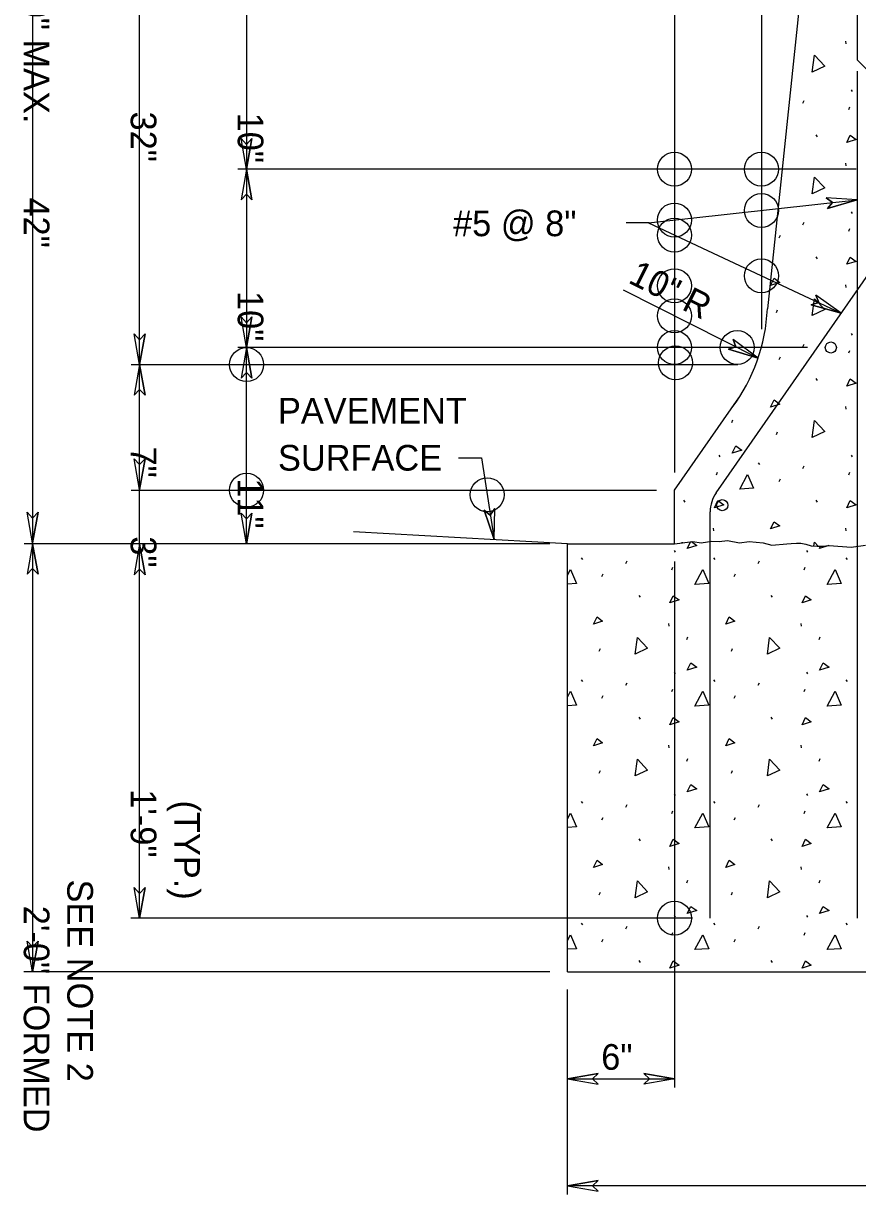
# Model space of a CAD drawing. Extents: x -26.5 to -19.2, y -3.6 to 6.6.
# Drawn here: x -25.3 to -23.351, y 0.225 to 2.961 of the extents above; entities that cross this region are included whole.
import ezdxf

# ---------------------------------------------------------------- set-up
doc = ezdxf.new("R2010")
doc.units = 0
for name, color, linetype in [('ANNO-WOUT', 7, 'Continuous'), ('DETL-DIMS', 7, 'Continuous'), ('DETL-PATT', 7, 'Continuous'), ('Level 10', 7, 'Continuous'), ('Level 12', 7, 'Continuous'), ('SECT-GRND_P', 7, 'Continuous'), ('SUBS-FOOT_P', 7, 'Continuous'), ('SUPR-PARA_P', 7, 'Continuous'), ('SUPR-RFRC', 7, 'Continuous')]:
    doc.layers.add(name, color=color, linetype=linetype)

msp = doc.modelspace()

# ---------------------------------------------------------------- linework, layer by layer
at = {"layer": 'ANNO-WOUT'}
for centre in [(-23.7787, 2.6205), (-23.5755, 2.6205), (-23.5755, 2.5241), (-23.7786, 2.5017), (-23.7786, 2.4664), (-23.5755, 2.3715), (-23.7787, 2.3482), (-23.7787, 2.2778), (-23.7787, 2.2039), (-23.6319, 2.2039), (-24.7787, 2.164), (-23.7761, 2.1681), (-24.7787, 1.8705), (-24.2163, 1.86), (-23.7787, 0.8705)]:
    msp.add_circle(centre, 0.0397, dxfattribs=at)
at = {"layer": 'DETL-DIMS'}
for p, q in [((-24.7787, 2.6205), (-24.7913, 2.692)), ((-24.7787, 2.6785), (-24.7913, 2.692)), ((-24.7787, 2.6205), (-24.7661, 2.692)), ((-24.7661, 2.692), (-24.7787, 2.6785)), ((-24.7787, 2.6205), (-24.7913, 2.549)), ((-24.7787, 2.6205), (-24.7661, 2.549)), ((-24.7787, 2.5625), (-24.7913, 2.549)), ((-24.7661, 2.549), (-24.7787, 2.5625)), ((-23.3516, 2.5488), (-23.424, 2.5535)), ((-23.4092, 2.5424), (-23.424, 2.5535)), ((-23.3516, 2.5488), (-23.4212, 2.5285)), ((-23.4212, 2.5285), (-23.4092, 2.5424)), ((-23.3889, 2.2843), (-23.4483, 2.3261)), ((-23.4415, 2.3089), (-23.4483, 2.3261)), ((-23.459, 2.3033), (-23.4415, 2.3089)), ((-23.3889, 2.2843), (-23.459, 2.3033)), ((-24.7787, 2.2039), (-24.7913, 2.2754)), ((-24.7787, 2.2619), (-24.7913, 2.2754)), ((-24.7787, 2.2039), (-24.7661, 2.2754)), ((-24.7661, 2.2754), (-24.7787, 2.2619)), ((-25.0287, 2.164), (-25.0413, 2.2355)), ((-25.0287, 2.222), (-25.0413, 2.2355)), ((-25.0287, 2.164), (-25.0161, 2.2355)), ((-25.0161, 2.2355), (-25.0287, 2.222)), ((-23.5832, 2.1793), (-23.6413, 2.2228)), ((-23.635, 2.2054), (-23.6413, 2.2228)), ((-24.7787, 2.2039), (-24.7913, 2.1324)), ((-24.7787, 2.2039), (-24.7661, 2.1324)), ((-23.6527, 2.2003), (-23.635, 2.2054)), ((-23.5832, 2.1793), (-23.6527, 2.2003)), ((-25.0287, 2.164), (-25.0413, 2.0925)), ((-25.0287, 2.164), (-25.0161, 2.0925)), ((-24.7787, 2.1459), (-24.7913, 2.1324)), ((-24.7661, 2.1324), (-24.7787, 2.1459)), ((-25.0287, 2.106), (-25.0413, 2.0925)), ((-25.0161, 2.0925), (-25.0287, 2.106)), ((-25.0287, 1.8723), (-25.0413, 1.9439)), ((-25.0287, 1.9303), (-25.0413, 1.9439)), ((-25.0287, 1.8723), (-25.0161, 1.9438)), ((-25.0161, 1.9438), (-25.0287, 1.9303)), ((-25.2787, 1.7473), (-25.2913, 1.8189)), ((-25.2787, 1.8053), (-25.2913, 1.8189)), ((-25.2787, 1.7473), (-25.2661, 1.8188)), ((-25.2661, 1.8188), (-25.2787, 1.8053)), ((-24.7787, 1.7455), (-24.7913, 1.817)), ((-24.7787, 1.8035), (-24.7913, 1.817)), ((-24.7787, 1.7455), (-24.7661, 1.817)), ((-24.7661, 1.817), (-24.7787, 1.8035)), ((-24.2004, 1.7551), (-24.2235, 1.8239)), ((-24.2235, 1.8239), (-24.2091, 1.8125)), ((-24.2091, 1.8125), (-24.1986, 1.8277)), ((-24.2004, 1.7551), (-24.1986, 1.8277)), ((-25.2787, 1.7455), (-25.2913, 1.674)), ((-25.2787, 1.7455), (-25.2661, 1.674)), ((-25.0287, 1.7441), (-25.0413, 1.6726)), ((-25.0287, 1.7441), (-25.0161, 1.6726)), ((-25.2787, 1.6875), (-25.2913, 1.674)), ((-25.2661, 1.674), (-25.2787, 1.6875)), ((-25.0287, 1.6861), (-25.0413, 1.6726)), ((-25.0161, 1.6726), (-25.0287, 1.6861)), ((-25.0287, 0.8705), (-25.0413, 0.942)), ((-25.0287, 0.9285), (-25.0413, 0.942)), ((-25.0287, 0.8705), (-25.0161, 0.942)), ((-25.0161, 0.942), (-25.0287, 0.9285)), ((-25.2787, 0.7455), (-25.2913, 0.817)), ((-25.2787, 0.8035), (-25.2913, 0.817)), ((-25.2787, 0.7455), (-25.2661, 0.817)), ((-25.2661, 0.817), (-25.2787, 0.8035)), ((-24.0286, 0.4955), (-23.9572, 0.508)), ((-24.0286, 0.4955), (-23.9571, 0.4828)), ((-23.9572, 0.508), (-23.9706, 0.4955)), ((-23.9706, 0.4955), (-23.9571, 0.4828)), ((-23.7787, 0.4955), (-23.8502, 0.4828)), ((-23.8367, 0.4955), (-23.8502, 0.4828)), ((-23.7787, 0.4955), (-23.8501, 0.508)), ((-23.8501, 0.508), (-23.8367, 0.4955)), ((-24.0286, 0.2455), (-23.9572, 0.258)), ((-23.9572, 0.258), (-23.9706, 0.2455)), ((-24.0286, 0.2455), (-23.9571, 0.2328)), ((-23.9706, 0.2455), (-23.9571, 0.2328))]:
    msp.add_line(p, q, dxfattribs=at)
for points in [[(-24.7661, 2.692), (-24.7787, 2.6205), (-24.7913, 2.692), (-24.7787, 2.6785)], [(-24.7661, 2.549), (-24.7787, 2.6205), (-24.7913, 2.549), (-24.7787, 2.5625)], [(-23.4212, 2.5285), (-23.3516, 2.5488), (-23.424, 2.5535), (-23.4092, 2.5424)], [(-23.459, 2.3033), (-23.3889, 2.2843), (-23.4483, 2.3261), (-23.4415, 2.3089)], [(-24.7661, 2.2754), (-24.7787, 2.2039), (-24.7913, 2.2754), (-24.7787, 2.2619)], [(-25.0161, 2.2355), (-25.0287, 2.164), (-25.0413, 2.2355), (-25.0287, 2.222)], [(-23.6527, 2.2003), (-23.5832, 2.1793), (-23.6413, 2.2228), (-23.635, 2.2054)], [(-24.7661, 2.1324), (-24.7787, 2.2039), (-24.7913, 2.1324), (-24.7787, 2.1459)], [(-25.0161, 2.0925), (-25.0287, 2.164), (-25.0413, 2.0925), (-25.0287, 2.106)], [(-25.0161, 1.9438), (-25.0287, 1.8723), (-25.0413, 1.9439), (-25.0287, 1.9303)], [(-25.2661, 1.8188), (-25.2787, 1.7473), (-25.2913, 1.8189), (-25.2787, 1.8053)], [(-24.7661, 1.817), (-24.7787, 1.7455), (-24.7913, 1.817), (-24.7787, 1.8035)], [(-24.2235, 1.8239), (-24.2004, 1.7551), (-24.1986, 1.8277), (-24.2091, 1.8125)], [(-25.2661, 1.674), (-25.2787, 1.7455), (-25.2913, 1.674), (-25.2787, 1.6875)], [(-25.0161, 1.6726), (-25.0287, 1.7441), (-25.0413, 1.6726), (-25.0287, 1.6861)], [(-25.0161, 0.942), (-25.0287, 0.8705), (-25.0413, 0.942), (-25.0287, 0.9285)], [(-25.2661, 0.817), (-25.2787, 0.7455), (-25.2913, 0.817), (-25.2787, 0.8035)], [(-23.9572, 0.508), (-24.0286, 0.4955), (-23.9571, 0.4828), (-23.9706, 0.4955)], [(-23.8501, 0.508), (-23.7787, 0.4955), (-23.8502, 0.4828), (-23.8367, 0.4955)], [(-23.9572, 0.258), (-24.0286, 0.2455), (-23.9571, 0.2328), (-23.9706, 0.2455)]]:
    msp.add_lwpolyline(points, close=True, dxfattribs=at)
at = {"layer": 'DETL-PATT'}
for p, q in [((-23.3789, 2.9193), (-23.3781, 2.9131)), ((-23.3657, 2.8056), (-23.3634, 2.8018)), ((-23.4786, 2.7747), (-23.4755, 2.7809)), ((-23.3711, 2.76), (-23.3688, 2.7662)), ((-23.4484, 2.7005), (-23.4453, 2.6959)), ((-23.3789, 2.6348), (-23.3781, 2.6286)), ((-23.3657, 2.5212), (-23.3634, 2.5173)), ((-23.4786, 2.4903), (-23.4755, 2.4965)), ((-23.5342, 2.4601), (-23.5311, 2.4663)), ((-23.3711, 2.4756), (-23.3688, 2.4818)), ((-23.4484, 2.4161), (-23.4453, 2.4114)), ((-23.3789, 2.3504), (-23.3781, 2.3442)), ((-23.5404, 2.2854), (-23.5381, 2.2916)), ((-23.3657, 2.2367), (-23.3634, 2.2329)), ((-23.4786, 2.2058), (-23.4755, 2.212)), ((-23.3711, 2.1911), (-23.3688, 2.1973)), ((-23.5342, 2.1757), (-23.5311, 2.1819)), ((-23.4484, 2.1316), (-23.4453, 2.127)), ((-23.3789, 2.0659), (-23.3781, 2.0597)), ((-23.6448, 2.0288), (-23.6424, 2.035)), ((-23.5404, 2.001), (-23.5381, 2.0072)), ((-23.6749, 1.9523), (-23.6726, 1.9484)), ((-23.3657, 1.9523), (-23.3634, 1.9484)), ((-23.5829, 1.9345), (-23.5798, 1.9307)), ((-23.4786, 1.9214), (-23.4755, 1.9276)), ((-23.6803, 1.9067), (-23.678, 1.9129)), ((-23.5342, 1.8912), (-23.5311, 1.8974)), ((-23.3711, 1.9067), (-23.3688, 1.9129)), ((-23.7576, 1.8472), (-23.7545, 1.8425)), ((-23.4484, 1.8472), (-23.4453, 1.8425)), ((-23.688, 1.7815), (-23.6873, 1.7753)), ((-23.3789, 1.7815), (-23.3781, 1.7753)), ((-23.7796, 1.7299), (-23.7773, 1.726)), ((-23.7487, 1.7345), (-23.7408, 1.7503)), ((-23.4704, 1.7299), (-23.4681, 1.726)), ((-23.4176, 1.7413), (-23.4395, 1.7345)), ((-23.4395, 1.7345), (-23.437, 1.7396)), ((-23.9968, 1.7121), (-23.9937, 1.7083)), ((-23.8924, 1.699), (-23.8893, 1.7052)), ((-23.6876, 1.7121), (-23.6845, 1.7083)), ((-23.5832, 1.699), (-23.5802, 1.7052)), ((-23.3784, 1.7121), (-23.3753, 1.7083)), ((-23.9481, 1.6688), (-23.945, 1.675)), ((-23.785, 1.6843), (-23.7827, 1.6905)), ((-23.6389, 1.6688), (-23.6358, 1.675)), ((-23.4758, 1.6843), (-23.4735, 1.6905)), ((-23.8623, 1.6248), (-23.8592, 1.6202)), ((-23.5531, 1.6248), (-23.55, 1.6202)), ((-23.7927, 1.5591), (-23.7919, 1.5529)), ((-23.4835, 1.5591), (-23.4828, 1.5529)), ((-23.7494, 1.522), (-23.7471, 1.5282)), ((-23.4402, 1.522), (-23.4379, 1.5282)), ((-23.9543, 1.4942), (-23.9519, 1.5003)), ((-23.6451, 1.4942), (-23.6428, 1.5003)), ((-23.9968, 1.4277), (-23.9937, 1.4238)), ((-23.7796, 1.4455), (-23.7773, 1.4416)), ((-23.6876, 1.4277), (-23.6845, 1.4238)), ((-23.4704, 1.4455), (-23.4681, 1.4416)), ((-23.3784, 1.4277), (-23.3753, 1.4238)), ((-23.8924, 1.4146), (-23.8893, 1.4207)), ((-23.785, 1.3999), (-23.7827, 1.406)), ((-23.5832, 1.4146), (-23.5802, 1.4207)), ((-23.4758, 1.3999), (-23.4735, 1.406)), ((-23.9481, 1.3844), (-23.945, 1.3906)), ((-23.6389, 1.3844), (-23.6358, 1.3906)), ((-23.8623, 1.3403), (-23.8592, 1.3357)), ((-23.5531, 1.3403), (-23.55, 1.3357)), ((-23.7927, 1.2746), (-23.7919, 1.2685)), ((-23.4835, 1.2746), (-23.4828, 1.2685)), ((-23.7494, 1.2375), (-23.7471, 1.2437)), ((-23.4402, 1.2375), (-23.4379, 1.2437)), ((-23.9543, 1.2097), (-23.9519, 1.2159)), ((-23.6451, 1.2097), (-23.6428, 1.2159)), ((-23.7796, 1.161), (-23.7773, 1.1572)), ((-23.4704, 1.161), (-23.4681, 1.1572)), ((-23.9968, 1.1432), (-23.9937, 1.1394)), ((-23.8924, 1.1301), (-23.8893, 1.1363)), ((-23.6876, 1.1432), (-23.6845, 1.1394)), ((-23.5832, 1.1301), (-23.5802, 1.1363)), ((-23.3784, 1.1432), (-23.3753, 1.1394)), ((-23.9481, 1.1), (-23.945, 1.1061)), ((-23.785, 1.1154), (-23.7827, 1.1216)), ((-23.6389, 1.1), (-23.6358, 1.1061)), ((-23.4758, 1.1154), (-23.4735, 1.1216)), ((-23.8623, 1.0559), (-23.8592, 1.0513)), ((-23.5531, 1.0559), (-23.55, 1.0513)), ((-23.7927, 0.9902), (-23.7919, 0.984)), ((-23.4835, 0.9902), (-23.4828, 0.984)), ((-23.7494, 0.9531), (-23.7471, 0.9593)), ((-23.4402, 0.9531), (-23.4379, 0.9593)), ((-23.9543, 0.9253), (-23.9519, 0.9315)), ((-23.6451, 0.9253), (-23.6428, 0.9315)), ((-23.7796, 0.8766), (-23.7773, 0.8727)), ((-23.4704, 0.8766), (-23.4681, 0.8727)), ((-23.9968, 0.8588), (-23.9937, 0.8549)), ((-23.8924, 0.8457), (-23.8893, 0.8518)), ((-23.6876, 0.8588), (-23.6845, 0.8549)), ((-23.5832, 0.8457), (-23.5802, 0.8518)), ((-23.3784, 0.8588), (-23.3753, 0.8549)), ((-23.9481, 0.8155), (-23.945, 0.8217)), ((-23.785, 0.831), (-23.7827, 0.8372)), ((-23.6389, 0.8155), (-23.6358, 0.8217)), ((-23.4758, 0.831), (-23.4735, 0.8372)), ((-23.8623, 0.7715), (-23.8592, 0.7668)), ((-23.5531, 0.7715), (-23.55, 0.7668))]:
    msp.add_line(p, q, dxfattribs=at)
for points in [[(-23.4569, 2.8474), (-23.4515, 2.8868), (-23.4276, 2.8613), (-23.4569, 2.8474)], [(-23.3758, 2.6827), (-23.368, 2.6997), (-23.3541, 2.6897), (-23.3758, 2.6827)], [(-23.4569, 2.5629), (-23.4515, 2.6023), (-23.4276, 2.5768), (-23.4569, 2.5629)], [(-23.3758, 2.3983), (-23.368, 2.4153), (-23.3541, 2.4052), (-23.3758, 2.3983)], [(-23.5543, 2.3488), (-23.5458, 2.3658), (-23.5327, 2.3558), (-23.5543, 2.3488)], [(-23.4569, 2.2785), (-23.4515, 2.3179), (-23.4276, 2.2924), (-23.4569, 2.2785)], [(-23.3758, 2.1138), (-23.368, 2.1309), (-23.3541, 2.1208), (-23.3758, 2.1138)], [(-23.5543, 2.0644), (-23.5458, 2.0814), (-23.5327, 2.0713), (-23.5543, 2.0644)], [(-23.4569, 1.994), (-23.4515, 2.0335), (-23.4276, 2.008), (-23.4569, 1.994)], [(-23.644, 1.9569), (-23.6355, 1.9739), (-23.6216, 1.9639), (-23.644, 1.9569)], [(-23.6262, 1.8727), (-23.6077, 1.9075), (-23.5937, 1.875), (-23.6262, 1.8727)], [(-23.6849, 1.8294), (-23.6772, 1.8464), (-23.6633, 1.8364), (-23.6849, 1.8294)], [(-23.3758, 1.8294), (-23.368, 1.8464), (-23.3541, 1.8364), (-23.3758, 1.8294)], [(-23.5543, 1.7799), (-23.5458, 1.7969), (-23.5327, 1.7869), (-23.5543, 1.7799)], [(-23.7609, 1.7478), (-23.7607, 1.749), (-23.7597, 1.7479)], [(-23.7388, 1.7505), (-23.7262, 1.7415), (-23.7487, 1.7345)], [(-23.4527, 1.7403), (-23.4515, 1.749), (-23.4426, 1.7396)], [(-24.0286, 1.6717), (-24.0215, 1.6851), (-24.0076, 1.6526), (-24.0286, 1.6511)], [(-23.7309, 1.6503), (-23.7123, 1.6851), (-23.6984, 1.6526), (-23.7309, 1.6503)], [(-23.4217, 1.6503), (-23.4031, 1.6851), (-23.3892, 1.6526), (-23.4217, 1.6503)], [(-23.7896, 1.607), (-23.7819, 1.624), (-23.768, 1.614), (-23.7896, 1.607)], [(-23.4804, 1.607), (-23.4727, 1.624), (-23.4588, 1.614), (-23.4804, 1.607)], [(-23.9682, 1.5575), (-23.9597, 1.5745), (-23.9465, 1.5645), (-23.9682, 1.5575)], [(-23.659, 1.5575), (-23.6505, 1.5745), (-23.6373, 1.5645), (-23.659, 1.5575)], [(-23.8708, 1.4872), (-23.8654, 1.5266), (-23.8414, 1.5011), (-23.8708, 1.4872)], [(-23.5616, 1.4872), (-23.5562, 1.5266), (-23.5322, 1.5011), (-23.5616, 1.4872)], [(-23.7487, 1.4501), (-23.7402, 1.4671), (-23.7262, 1.4571), (-23.7487, 1.4501)], [(-23.4395, 1.4501), (-23.431, 1.4671), (-23.4171, 1.4571), (-23.4395, 1.4501)], [(-24.0286, 1.3872), (-24.0215, 1.4006), (-24.0076, 1.3682), (-24.0286, 1.3667)], [(-23.7309, 1.3659), (-23.7123, 1.4006), (-23.6984, 1.3682), (-23.7309, 1.3659)], [(-23.4217, 1.3659), (-23.4031, 1.4006), (-23.3892, 1.3682), (-23.4217, 1.3659)], [(-23.7896, 1.3226), (-23.7819, 1.3396), (-23.768, 1.3295), (-23.7896, 1.3226)], [(-23.4804, 1.3226), (-23.4727, 1.3396), (-23.4588, 1.3295), (-23.4804, 1.3226)], [(-23.9682, 1.2731), (-23.9597, 1.2901), (-23.9465, 1.2801), (-23.9682, 1.2731)], [(-23.659, 1.2731), (-23.6505, 1.2901), (-23.6373, 1.2801), (-23.659, 1.2731)], [(-23.8708, 1.2028), (-23.8654, 1.2422), (-23.8414, 1.2167), (-23.8708, 1.2028)], [(-23.5616, 1.2028), (-23.5562, 1.2422), (-23.5322, 1.2167), (-23.5616, 1.2028)], [(-23.7487, 1.1657), (-23.7402, 1.1827), (-23.7262, 1.1726), (-23.7487, 1.1657)], [(-23.4395, 1.1657), (-23.431, 1.1827), (-23.4171, 1.1726), (-23.4395, 1.1657)], [(-24.0286, 1.1028), (-24.0215, 1.1162), (-24.0076, 1.0837), (-24.0286, 1.0822)], [(-23.7309, 1.0814), (-23.7123, 1.1162), (-23.6984, 1.0837), (-23.7309, 1.0814)], [(-23.4217, 1.0814), (-23.4031, 1.1162), (-23.3892, 1.0837), (-23.4217, 1.0814)], [(-23.7896, 1.0381), (-23.7819, 1.0551), (-23.768, 1.0451), (-23.7896, 1.0381)], [(-23.4804, 1.0381), (-23.4727, 1.0551), (-23.4588, 1.0451), (-23.4804, 1.0381)], [(-23.9682, 0.9887), (-23.9597, 1.0057), (-23.9465, 0.9956), (-23.9682, 0.9887)], [(-23.659, 0.9887), (-23.6505, 1.0057), (-23.6373, 0.9956), (-23.659, 0.9887)], [(-23.8708, 0.9183), (-23.8654, 0.9577), (-23.8414, 0.9322), (-23.8708, 0.9183)], [(-23.5616, 0.9183), (-23.5562, 0.9577), (-23.5322, 0.9322), (-23.5616, 0.9183)], [(-23.7487, 0.8812), (-23.7402, 0.8982), (-23.7262, 0.8882), (-23.7487, 0.8812)], [(-23.4395, 0.8812), (-23.431, 0.8982), (-23.4171, 0.8882), (-23.4395, 0.8812)], [(-24.0286, 0.8184), (-24.0215, 0.8318), (-24.0076, 0.7993), (-24.0286, 0.7978)], [(-23.7309, 0.797), (-23.7123, 0.8318), (-23.6984, 0.7993), (-23.7309, 0.797)], [(-23.4217, 0.797), (-23.4031, 0.8318), (-23.3892, 0.7993), (-23.4217, 0.797)], [(-23.7896, 0.7537), (-23.7819, 0.7707), (-23.768, 0.7606), (-23.7896, 0.7537)], [(-23.4804, 0.7537), (-23.4727, 0.7707), (-23.4588, 0.7606), (-23.4804, 0.7537)]]:
    msp.add_lwpolyline(points, dxfattribs=at)
at = {"layer": 'Level 10'}
for p, q in [((-23.7787, 6.5163), (-23.7787, 1.9121)), ((-23.5755, 6.0163), (-23.5755, 2.2464)), ((-25.2787, 3.4973), (-25.2787, 1.7455)), ((-25.0287, 2.1654), (-25.0287, 3.4973)), ((-24.7787, 3.0372), (-24.7787, 2.6205)), ((-23.3542, 2.6205), (-24.7995, 2.6205)), ((-24.7787, 2.6205), (-24.7787, 2.2039)), ((-23.8396, 2.4949), (-23.3516, 2.5488)), ((-23.8377, 2.4949), (-23.8916, 2.4949)), ((-23.8396, 2.4949), (-23.3889, 2.2843)), ((-23.5832, 2.1793), (-23.8976, 2.3378)), ((-23.4679, 2.2039), (-24.7995, 2.2039)), ((-24.7787, 1.7455), (-24.7787, 2.2039)), ((-25.0486, 2.164), (-23.6304, 2.164)), ((-25.0287, 1.8723), (-25.0287, 2.1654)), ((-24.2832, 1.9463), (-24.2294, 1.9463)), ((-24.2294, 1.9463), (-24.2004, 1.7551)), ((-25.0486, 1.8705), (-23.8203, 1.8705)), ((-25.0287, 1.7455), (-25.0287, 1.8723)), ((-24.0703, 1.7455), (-25.2986, 1.7455)), ((-25.2787, 1.7455), (-25.2787, 0.7455)), ((-25.0287, 0.8705), (-25.0287, 1.7455)), ((-23.7787, 1.7039), (-23.7787, 0.4747)), ((-23.7369, 0.8705), (-25.0495, 0.8705)), ((-24.0703, 0.7455), (-25.2995, 0.7455)), ((-24.0286, 0.2247), (-24.0286, 0.7039)), ((-24.0286, 0.4955), (-23.7787, 0.4955)), ((-22.237, 0.2455), (-24.0286, 0.2455))]:
    msp.add_line(p, q, dxfattribs=at)
at = {"layer": 'SECT-GRND_P'}
msp.add_line((-24.0286, 1.7455), (-24.5286, 1.7735), dxfattribs=at)
at = {"layer": 'SUBS-FOOT_P'}
for p, q in [((-24.0286, 1.7455), (-23.7786, 1.7455)), ((-24.0286, 0.7455), (-24.0286, 1.7455)), ((-24.0286, 0.7455), (-22.237, 0.7455))]:
    msp.add_line(p, q, dxfattribs=at)
msp.add_lwpolyline([(-23.7786, 1.7455), (-23.7355, 1.751), (-23.7163, 1.7474), (-23.6914, 1.7518), (-23.6739, 1.7504), (-23.6544, 1.7532), (-23.6268, 1.7474), (-23.6037, 1.7505), (-23.571, 1.7475), (-23.5513, 1.7423), (-23.5159, 1.7454), (-23.5056, 1.7463), (-23.4935, 1.7467), (-23.4832, 1.7467), (-23.472, 1.7445), (-23.4595, 1.7409), (-23.4452, 1.7396), (-23.4326, 1.7396), (-23.4174, 1.7413), (-23.3653, 1.7373), (-23.3322, 1.7421)], dxfattribs=at)
at = {"layer": 'SUPR-PARA_P'}
for p, q in [((-23.4349, 3.4955), (-23.5616, 2.2941)), ((-23.7786, 1.8705), (-23.6282, 2.0865)), ((-23.7786, 1.7455), (-23.7786, 1.8705))]:
    msp.add_line(p, q, dxfattribs=at)
msp.add_arc((-23.9778, 2.3132), 0.4167, 323.2474, 357.3682, dxfattribs=at)
at = {"layer": 'SUPR-RFRC'}
for p, q in [((-23.3516, 5.2664), (-23.3516, 2.8757)), ((-23.3255, 2.8497), (-23.3516, 2.8757)), ((-23.3516, 2.8497), (-23.3516, 0.8705)), ((-23.6813, 1.8645), (-23.2087, 2.5431)), ((-23.6953, 0.8705), (-23.6953, 1.8199))]:
    msp.add_line(p, q, dxfattribs=at)
for centre in [(-23.4132, 2.2039), (-23.6669, 1.8355)]:
    msp.add_circle(centre, 0.013, dxfattribs=at)
msp.add_arc((-23.6172, 1.8199), 0.0781, 145.1455, 180, dxfattribs=at)

# ---------------------------------------------------------------- texts
at = {"layer": 'Level 12'}
for s, rotation, p in [('VARIES 1\'-6" TO 4\'-0" MAX.', 270, (-25.2995, 3.7381)), ('32"', 270, (-25.0495, 2.7552)), ('10"', 270, (-24.7995, 2.7527)), ('42"', 270, (-25.2995, 2.5545)), ('10" R', 333.3856, (-23.8893, 2.3565)), ('10"', 270, (-24.7995, 2.336)), ('7"', 270, (-25.0495, 1.9727)), ('11"', 270, (-24.7995, 1.8985)), ('3"', 270, (-25.0495, 1.7628)), ('1\'-9"', 270, (-25.0495, 1.1719)), ('(TYP.)', 270, (-24.9478, 1.1455)), ('SEE NOTE 2', 270, (-25.1978, 0.9609)), ('2\'-0" FORMED', 270, (-25.2995, 0.8996))]:
    msp.add_text(s, height=0.06001, rotation=rotation, dxfattribs=at).set_placement(p)
for s, p in [('#5 @ 8"', (-24.2961, 2.464)), ('PAVEMENT ', (-24.7053, 2.0263)), ('SURFACE', (-24.7053, 1.9163)), ('6"', (-23.9498, 0.5163))]:
    msp.add_text(s, height=0.06001, dxfattribs=at).set_placement(p)

doc.saveas('drawing.dxf')
